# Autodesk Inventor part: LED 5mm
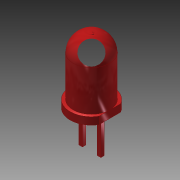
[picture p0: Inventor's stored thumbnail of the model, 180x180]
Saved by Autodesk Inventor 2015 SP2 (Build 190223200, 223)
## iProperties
Created: 2012-08
Part Number: LED 5mm
Material: PC/ABS-Kunststoff
Document SubType Name: Modeling
Designer: rYan
Density: 1.493 g/cm^3
Mass: 0.251708 g
Surface Area: 1.94358 cm^2
Volume: 0.168592 cm^3
Appearance: Hellrot
Author: rYan
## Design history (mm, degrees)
sketch "Skizze1"
  geometry: L1 (0, 0)-(0, 9); L2 (0, 0)-(2.9, 0); L3 (2.9, 0)-(2.9, 1); L4 (2.9, 1)-(2.5, 1); L5 (2.5, 1)-(2.5, 6.5); A1 r 2.5 centre (0, 6.5) between (2.5, 6.5) and (0, 9)
  constraints: 10 end point, 2 parallel, 2 perpendicular, 2 point on circle, 1 centre point, 1 point on line, 1 tangent, 1 vertical
  dimensions: "d0" = 5.8 diameter of L3 L1; "d2" = 5 diameter of L5 L1; "d3" = 9 distance of L1.start L1.end; "d4" = 1 distance of L2.end L3.end
revolve "Umdrehung1" sketch "Skizze1" stored, may be unused: angle "d5" = 90 deg
workplane "Arbeitsebene2"
sketch "Skizze2"
  geometry: L1 (-2.9, -3.75)-(2.9, -3.75) reference; L2 (-2.9, -2.75)-(2.9, -2.75) reference; L3 (-2.9, -2.75)-(2.9, -2.75); L4 (2.9, -2.75)-(2.9, -3.75); L5 (2.9, -3.75)-(-2.9, -3.75); L6 (-2.9, -3.75)-(-2.9, -2.75); 1 further point
  constraints: 8 end point, 2 parallel, 1 horizontal, 1 perpendicular
extrude "Extrusion1" cut sketch "Skizze2" distance "d6" = 1; taper "d7" = 0 deg
sketch "Skizze3"
  geometry: L1 (-1.5, 0.225)-(-1, 0.225); L2 (-1, 0.225)-(-1, -0.225); L3 (-1, -0.225)-(-1.5, -0.225); L4 (-1.5, -0.225)-(-1.5, 0.225); L5 (1, 0.225)-(1.5, 0.225); L6 (1.5, 0.225)-(1.5, -0.225); L7 (1.5, -0.225)-(1, -0.225); L8 (1, -0.225)-(1, 0.225); L9 (0, -4.06)-(0, 4.06) reference; L10 (-3.58, 0)-(3.98, 0) reference; 1 further point
  constraints: 16 end point, 4 parallel, 2 horizontal, 2 perpendicular, 5 other
  dimensions: "d8" = 0.5 distance of L1.start L1.end; "d10" = 0.45 distance of L1.end L2.end; "d11" = 3 distance between parallel lines of L6 L4
extrude "Extrusion2" join sketch "Skizze3" distance "d12" = 5; taper "d13" = 0 deg
node "Volumenkörper1"
node "Projizierte Kontur1"
